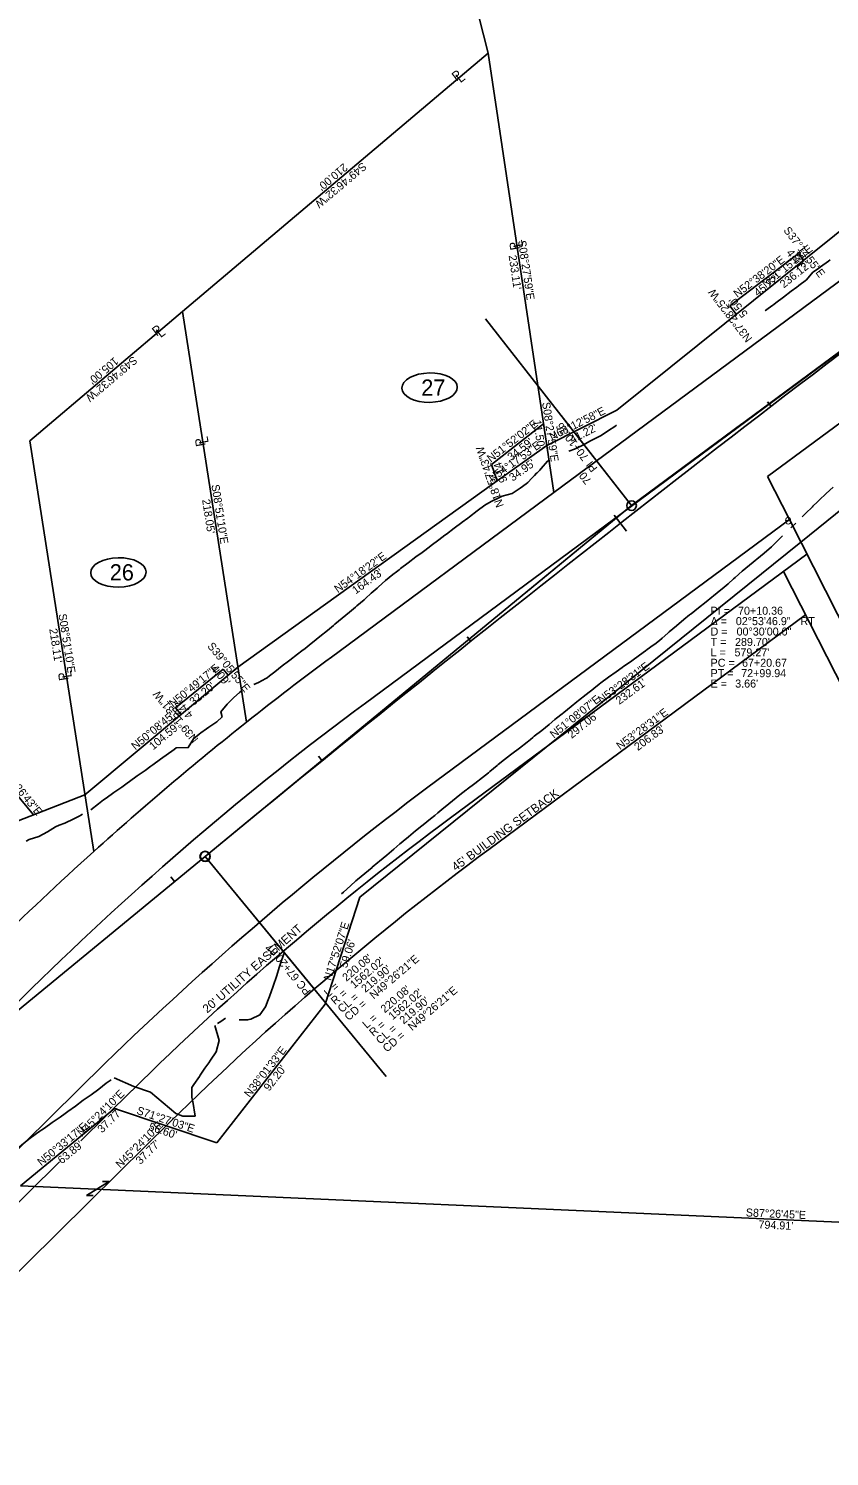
# Model space of a CAD drawing. Extents: x 1145508 to 2262867, y -3126236 to 2021677.
# Drawn here: x 1149547 to 1149967, y 2018793 to 2019543 of the extents above; entities that cross this region are included whole.
import ezdxf

# ---------------------------------------------------------------- set-up
doc = ezdxf.new("R2010")
doc.units = 0
for name, color, linetype in [('Default', 7, 'Continuous'), ('DSN_DRFT_Guideline-No-Plot', 7, 'Continuous'), ('DSN_RDWY_Alignment', 7, 'Continuous'), ('DSN_RDWY_Alignment Annotation', 7, 'Continuous'), ('DSN_RDWY_Const Limits', 7, 'Continuous'), ('DSN_ROW_Annotation', 7, 'Continuous'), ('DSN_ROW_Esmnt', 7, 'Continuous'), ('DSN_ROW_Line', 7, 'Continuous'), ('DSN_ROW_Line-Annotation', 7, 'Continuous'), ('DSN_ROW_Prop-Line', 7, 'Continuous'), ('DSN_ROW_Prop-Line-Annotation', 7, 'Continuous'), ('E_Const Align', 7, 'Continuous'), ('EX_QSECTION', 7, 'Continuous'), ('EX_ROW', 7, 'Continuous'), ('EX_ROW_ANNOT', 7, 'Continuous')]:
    doc.layers.add(name, color=color, linetype=linetype)

msp = doc.modelspace()

# ---------------------------------------------------------------- linework, layer by layer
at = {"layer": 'Default'}
for p, q in [((1150568.87, 2019814.51), (1149723.97, 2019188.76)), ((1149548.89, 2019038.9), (1148996.69, 2018494.41))]:
    msp.add_line(p, q, dxfattribs=at)
msp.add_arc((1150698.28, 2017873.24), 1637.02, 126.5246, 134.5973, dxfattribs=at)
at = {"layer": 'DSN_RDWY_Alignment'}
for p, q in [((1149863.59, 2019292.35), (1150096.32, 2019464.87)), ((1149639.88, 2019108.3), (1149863.59, 2019292.35))]:
    msp.add_line(p, q, dxfattribs=at)
for points in [[(1149863.59, 2019292.35), (1149787.06, 2019390.33)], [(1149639.88, 2019108.3), (1149734.93, 2018992.77)]]:
    msp.add_lwpolyline(points, dxfattribs=at)
for centre in [(1149863.59, 2019292.35), (1149639.88, 2019108.3)]:
    msp.add_circle(centre, 2.5, dxfattribs=at)
at = {"layer": 'DSN_RDWY_Alignment Annotation'}
for p, q in [((1149934.92, 2019346.79), (1149936.75, 2019344.41)), ((1149863.59, 2019292.35), (1149826.66, 2019339.64)), ((1149826.66, 2019339.64), (1149826.66, 2019339.64)), ((1149863.59, 2019292.35), (1149921.44, 2019335.23)), ((1149863.59, 2019292.35), (1149807.99, 2019246.61)), ((1149854.44, 2019287.33), (1149860.99, 2019278.96)), ((1149777.38, 2019223.49), (1149779.25, 2019221.15)), ((1149699.43, 2019160.82), (1149701.32, 2019158.49)), ((1149639.88, 2019108.3), (1149639.88, 2019108.3)), ((1149641.58, 2019106.23), (1149697.06, 2019038.8)), ((1149622.01, 2019097.48), (1149623.92, 2019095.17)), ((1149697.06, 2019038.8), (1149697.06, 2019038.8))]:
    msp.add_line(p, q, dxfattribs=at)
msp.add_circle((1149639.88, 2019108.3), 2.67, dxfattribs=at)
at = {"layer": 'DSN_RDWY_Const Limits'}
for p, q in [((1149933.84, 2019394.8), (1149933.59, 2019394.64)), ((1149813.81, 2019309.34), (1149814.09, 2019309.64))]:
    msp.add_line(p, q, dxfattribs=at)
for points in [[(1149933.84, 2019394.8), (1149935.26, 2019395.75), (1149937.66, 2019397.57), (1149938.2, 2019397.97), (1149939.26, 2019398.78), (1149943.26, 2019401.81), (1149947.27, 2019404.83), (1149950.2, 2019407.03), (1149951.08, 2019407.7), (1149951.28, 2019407.85), (1149955.3, 2019410.86), (1149958.61, 2019414.79), (1149961.58, 2019416.87), (1149962.72, 2019417.67), (1149966.81, 2019420.59), (1149967.8, 2019421.29)], [(1149830.76, 2019320.89), (1149833.71, 2019321.96), (1149838.33, 2019324.2), (1149841.65, 2019326.21), (1149842.71, 2019326.74), (1149847.29, 2019329.03), (1149848.2, 2019329.54), (1149851.54, 2019331.74), (1149854.76, 2019333.85), (1149855.74, 2019334.52)], [(1149814.09, 2019309.64), (1149815.41, 2019311.02), (1149816.15, 2019311.81), (1149819.55, 2019315.61), (1149820.38, 2019316.55)], [(1149665.48, 2019198.56), (1149667.97, 2019199.6), (1149671.79, 2019201.55), (1149672.44, 2019202.06), (1149673.62, 2019202.98), (1149676.4, 2019205.15), (1149680.38, 2019208.21), (1149683.7, 2019210.73), (1149684.38, 2019211.26), (1149688.34, 2019214.35), (1149690.67, 2019216.17), (1149692.33, 2019217.41), (1149695.57, 2019219.94), (1149696.27, 2019220.52), (1149700.15, 2019223.7), (1149704.03, 2019226.89), (1149707.18, 2019229.48), (1149707.44, 2019229.7), (1149707.91, 2019230.08), (1149711.81, 2019233.25), (1149715.66, 2019236.48), (1149718.75, 2019239.08), (1149719.51, 2019239.71), (1149723.32, 2019242.97), (1149723.96, 2019243.55), (1149727.05, 2019246.36), (1149730.07, 2019249.11), (1149730.77, 2019249.74), (1149734.5, 2019253.12), (1149738.41, 2019256.28), (1149740.26, 2019257.67), (1149741.63, 2019258.73), (1149742.41, 2019259.32), (1149746.39, 2019262.38), (1149750.41, 2019265.4), (1149753.67, 2019267.7), (1149754.5, 2019268.33), (1149757.51, 2019270.61), (1149758.5, 2019271.37), (1149762.51, 2019274.4), (1149765.66, 2019276.78), (1149766.52, 2019277.43), (1149770.53, 2019280.45), (1149774.53, 2019283.49), (1149774.7, 2019283.62), (1149777.66, 2019285.84), (1149778.54, 2019286.51), (1149782.55, 2019289.54), (1149786.56, 2019292.57), (1149789.97, 2019294.58), (1149790.98, 2019295.08), (1149792.53, 2019295.81), (1149795.64, 2019297.27), (1149800.92, 2019298.68), (1149804.16, 2019300.86), (1149805.08, 2019301.52), (1149808.34, 2019303.87), (1149809.11, 2019304.52), (1149811.32, 2019306.77), (1149812.66, 2019308.13), (1149813.81, 2019309.34)], [(1149952.99, 2019286.44), (1149954.84, 2019288.22), (1149958.43, 2019291.71), (1149958.71, 2019291.99), (1149961.06, 2019294.29), (1149962, 2019295.22), (1149965.59, 2019298.73), (1149969.32, 2019302.03)], [(1149947.13, 2019280.7), (1149947.67, 2019281.22), (1149949.7, 2019283.23)], [(1149711.4, 2019088.55), (1149712.47, 2019089.47), (1149716.12, 2019092.86), (1149718.98, 2019095.48), (1149719.83, 2019096.19), (1149723.66, 2019099.36), (1149727.49, 2019102.53), (1149727.52, 2019102.55), (1149730.5, 2019105.02), (1149731.33, 2019105.7), (1149735.14, 2019108.9), (1149738.93, 2019112.12), (1149742.11, 2019114.81), (1149742.73, 2019115.33), (1149743.86, 2019116.29), (1149746.53, 2019118.55), (1149750.32, 2019121.76), (1149753.56, 2019124.32), (1149754.22, 2019124.85), (1149758.13, 2019127.93), (1149760.39, 2019129.79), (1149761.97, 2019131.09), (1149765.11, 2019133.69), (1149765.8, 2019134.26), (1149769.65, 2019137.41), (1149773.51, 2019140.55), (1149776.67, 2019143.06), (1149776.94, 2019143.26), (1149777.42, 2019143.63), (1149781.4, 2019146.61), (1149785.38, 2019149.6), (1149788.46, 2019152.16), (1149789.21, 2019152.78), (1149793.04, 2019155.96), (1149793.69, 2019156.5), (1149796.9, 2019159.09), (1149800.12, 2019161.53), (1149800.87, 2019162.09), (1149804.82, 2019165.12), (1149808.77, 2019168.14), (1149810.51, 2019169.64), (1149811.81, 2019170.75), (1149812.55, 2019171.37), (1149816.48, 2019174.42), (1149820.37, 2019177.53), (1149823.37, 2019180.09), (1149824.17, 2019180.74), (1149827.11, 2019183.05), (1149828.08, 2019183.81), (1149831.96, 2019186.92), (1149834.94, 2019189.46), (1149835.78, 2019190.11), (1149839.71, 2019193.16), (1149843.61, 2019196.24), (1149843.78, 2019196.38), (1149846.6, 2019198.71), (1149847.49, 2019199.36), (1149851.53, 2019202.27), (1149855.57, 2019205.18), (1149858.73, 2019207.45), (1149859.61, 2019208.09), (1149860.96, 2019209.05), (1149863.66, 2019210.99), (1149867.7, 2019213.89), (1149870.84, 2019216.14), (1149871.75, 2019216.79), (1149874.99, 2019219.11), (1149875.8, 2019219.69), (1149878.25, 2019221.59), (1149879.63, 2019222.86), (1149882.53, 2019225.5), (1149883.35, 2019226.18), (1149887.17, 2019229.36), (1149891, 2019232.54), (1149894.03, 2019234.98), (1149894.55, 2019235.4), (1149894.88, 2019235.66), (1149898.75, 2019238.78), (1149902.64, 2019241.88), (1149905.62, 2019244.27), (1149906.52, 2019244.99), (1149910.4, 2019248.11), (1149911.18, 2019248.77), (1149914.18, 2019251.35), (1149917.03, 2019253.87), (1149917.92, 2019254.64), (1149921.67, 2019257.93), (1149925.46, 2019261.16), (1149927.37, 2019262.72), (1149928.39, 2019263.54), (1149929.32, 2019264.29), (1149933.13, 2019267.49), (1149936.92, 2019270.72), (1149939.65, 2019273.33), (1149940.53, 2019274.18), (1149942.81, 2019276.42)], [(1149580.04, 2019132.77), (1149584, 2019135.82), (1149586.69, 2019137.89), (1149587.98, 2019138.84), (1149592.06, 2019141.76), (1149596.14, 2019144.67), (1149599.07, 2019146.76), (1149600.22, 2019147.58), (1149604.29, 2019150.5), (1149604.84, 2019150.89), (1149608.39, 2019153.43), (1149611.46, 2019155.61), (1149612.49, 2019156.35), (1149616.57, 2019159.29), (1149620.66, 2019162.23), (1149622.4, 2019163.48), (1149623.7, 2019164.41), (1149624.75, 2019165.17), (1149631.05, 2019165.4), (1149633.73, 2019170.05), (1149636.84, 2019172.46), (1149637.72, 2019173.1), (1149640.62, 2019175.24), (1149641.77, 2019176.09), (1149645.99, 2019178.86), (1149648.9, 2019181.48), (1149648.22, 2019184.08), (1149651.43, 2019188.09), (1149655.03, 2019191.63), (1149655.05, 2019191.65), (1149657.89, 2019194.36), (1149658.73, 2019195.03), (1149659.41, 2019195.42)], [(1149546.1, 2019116.24), (1149547.6, 2019117.1), (1149552.67, 2019118.8), (1149557.21, 2019121.15), (1149559.98, 2019122.94), (1149561.47, 2019123.86), (1149563.43, 2019124.62), (1149566.37, 2019125.77), (1149571.04, 2019127.96), (1149574.11, 2019129.59), (1149574.64, 2019129.88), (1149575.54, 2019130.36)], [(1149657.78, 2019022.53), (1149662.22, 2019022.5), (1149662.89, 2019022.62), (1149663.92, 2019022.94), (1149668.66, 2019025.05), (1149671.64, 2019029.29), (1149672.95, 2019033.04), (1149673.6, 2019034.79), (1149675.6, 2019040.22), (1149677.52, 2019045.75), (1149678.77, 2019049.89), (1149679.27, 2019051.49), (1149681.16, 2019057.07), (1149681.42, 2019057.81)], [(1149592.17, 2018992.1), (1149602.46, 2018987.46), (1149611.33, 2018984.55), (1149624.54, 2018973.44), (1149628.15, 2018971.98), (1149634.62, 2018971.99), (1149633.55, 2018979.58), (1149633, 2018981.82), (1149632.91, 2018986.98), (1149633.96, 2018988.53), (1149636.9, 2018992.83), (1149637.28, 2018993.39), (1149639.83, 2018997.13), (1149641.77, 2018999.97), (1149642.77, 2019001.43), (1149645.7, 2019005.73), (1149647.32, 2019011.63), (1149645.05, 2019019.54)], [(1149646.41, 2019020.62), (1149648.1, 2019021.71), (1149650.56, 2019023.44)], [(1149528.11, 2018944.05), (1149530.65, 2018946.11), (1149531.99, 2018947.2), (1149535.86, 2018950.37), (1149539.74, 2018953.53), (1149542.23, 2018955.56), (1149543.61, 2018956.68), (1149547.49, 2018959.84), (1149551.48, 2018962.86), (1149553.13, 2018964), (1149554.34, 2018964.84), (1149555.6, 2018965.72), (1149559.72, 2018968.59), (1149563.81, 2018971.49), (1149566.45, 2018973.36), (1149567.89, 2018974.39), (1149571.98, 2018977.29), (1149575.92, 2018980.37), (1149578.55, 2018982.18), (1149580.12, 2018983.14), (1149584.19, 2018986.06), (1149588.03, 2018989.26), (1149590.65, 2018991.09)]]:
    msp.add_lwpolyline(points, dxfattribs=at)
at = {"layer": 'DSN_ROW_Esmnt'}
for p, q in [((1149915.19, 2019397.19), (1149951.12, 2019424.63)), ((1149951.12, 2019424.63), (1149953.79, 2019421.12)), ((1149918.53, 2019392.83), (1149915.19, 2019397.19)), ((1149790.16, 2019313.98), (1149817.37, 2019335.34)), ((1149817.37, 2019335.34), (1149819.06, 2019323.97)), ((1149793.13, 2019305.33), (1149790.16, 2019313.98)), ((1149624.45, 2019186.17), (1149649.41, 2019206.51)), ((1149649.41, 2019206.51), (1149651.99, 2019203.33)), ((1149627.28, 2019182.71), (1149624.45, 2019186.17)), ((1149533.36, 2019150.15), (1149549.85, 2019130.11))]:
    msp.add_line(p, q, dxfattribs=at)
at = {"layer": 'DSN_ROW_Line'}
for p, q in [((1149855.86, 2019342.54), (1150040.02, 2019490.31)), ((1149952.32, 2019273.26), (1150109.19, 2019399.67)), ((1149819.06, 2019323.97), (1149855.86, 2019342.54)), ((1149790.68, 2019303.57), (1149819.06, 2019323.97)), ((1149657.14, 2019207.63), (1149790.68, 2019303.57)), ((1149721.02, 2019086.86), (1149952.32, 2019273.26)), ((1149576.85, 2019140.61), (1149657.14, 2019207.63)), ((1149487.33, 2019105.8), (1149576.85, 2019140.61)), ((1149702.9, 2019030.65), (1149721.02, 2019086.86)), ((1149646.11, 2018958.02), (1149702.9, 2019030.65)), ((1149543.1, 2018935.44), (1149592.44, 2018976.03)), ((1149592.44, 2018976.03), (1149646.11, 2018958.02))]:
    msp.add_line(p, q, dxfattribs=at)
at = {"layer": 'DSN_ROW_Line-Annotation'}
for centre in [(1149757.65, 2019354.26), (1149594.42, 2019257.31)]:
    msp.add_ellipse(centre, major_axis=(14.54, 0.23), ratio=0.529773, dxfattribs=at)
at = {"layer": 'DSN_ROW_Prop-Line'}
for p, q in [((1149710.44, 2019832.55), (1149788.42, 2019529.81)), ((1149788.42, 2019529.81), (1149628.08, 2019394.19)), ((1149788.42, 2019529.81), (1149822.74, 2019299.24)), ((1149628.08, 2019394.19), (1149547.91, 2019326.39)), ((1149628.08, 2019394.19), (1149661.64, 2019178.75)), ((1149547.91, 2019326.39), (1149581.48, 2019110.87)), ((1149946.36, 2019285.02), (1150027.42, 2019125.25)), ((1149768.61, 2019128.48), (1149955.54, 2019266.93)), ((1149943.31, 2019257.87), (1150019.77, 2019107.18)), ((1149788.69, 2019111.93), (1149954.9, 2019235.03)), ((1149574.65, 2018958.97), (1149601.55, 2018985.49)), ((1149594.73, 2018942.42), (1149621.63, 2018968.94)), ((1149295.7, 2018683.91), (1149563.53, 2018948)), ((1149320.31, 2018671.82), (1149594.73, 2018942.42))]:
    msp.add_line(p, q, dxfattribs=at)
for centre in [(1150698.28, 2017873.24), (1150718.36, 2017856.69)]:
    msp.add_arc(centre, 1562.02, 126.5246, 134.5973, dxfattribs=at)
at = {"layer": 'DSN_ROW_Prop-Line-Annotation'}
for p, q in [((1149577.71, 2018930.36), (1149589.56, 2018937.74)), ((1149589.56, 2018937.74), (1149586.01, 2018937.74)), ((1149581.25, 2018930.36), (1149577.71, 2018930.36))]:
    msp.add_line(p, q, dxfattribs=at)
at = {"layer": 'E_Const Align'}
msp.add_line((1148677.53, 2018316.54), (1149639.88, 2019108.3), dxfattribs=at)
msp.add_arc((1156920.36, 2010259.18), 11459.16, 126.548983, 129.445337, dxfattribs=at)
msp.add_arc((1156920.36, 2010259.18), 11459.16, 126.548983, 129.445337, dxfattribs=at)
at = {"layer": 'EX_QSECTION'}
msp.add_line((1149543.1, 2018935.44), (1150337.23, 2018900.01), dxfattribs=at)
at = {"layer": 'EX_ROW'}
for p, q in [((1149822.74, 2019299.24), (1150218.47, 2019592.32)), ((1149934.89, 2019307.63), (1150095.5, 2019426.58)), ((1149946.36, 2019285.02), (1149934.89, 2019307.63)), ((1149706.12, 2019212.86), (1149822.74, 2019299.24)), ((1149756.71, 2019144.56), (1149946.36, 2019285.02)), ((1149952.32, 2019273.26), (1149946.36, 2019285.02)), ((1149523.2, 2018936.33), (1149587.51, 2018999.73))]:
    msp.add_line(p, q, dxfattribs=at)
for centre, radius, start, end in [((1150698.28, 2017873.24), 1667.02, 126.5246, 128.45139), ((1150698.28, 2017873.24), 1667.02, 128.45139, 132.0621), ((1150799.18, 2017755.35), 1736.85, 126.88494, 134.23696), ((1150698.28, 2017873.24), 1667.02, 132.0621, 134.5973)]:
    msp.add_arc(centre, radius, start, end, dxfattribs=at)

# ---------------------------------------------------------------- texts
at = {"layer": 'DSN_DRFT_Guideline-No-Plot'}
for rotation, p in [(352.30493, (1149951.08, 2019424.59)), (262.99544, (1149953.75, 2019421.16)), (82.41743, (1149915.23, 2019397.15)), (354.13868, (1149649.37, 2019206.46)), (84.21868, (1149624.5, 2019186.13))]:
    msp.add_text('+', height=0.1, rotation=rotation, dxfattribs=at).set_placement(p)
for p in [(1149952.79, 2019420.12), (1149917.53, 2019391.83)]:
    msp.add_text('b', height=2, dxfattribs=at).set_placement(p)
at = {"layer": 'DSN_RDWY_Alignment Annotation'}
for s, rotation, p in [('70+10.36', 127.99716, (1149841.38, 2019317.86)), ('PI ', 127.99716, (1149845.95, 2019312.02)), ('70', 128.04868, (1149842.85, 2019305.54)), ('67+20.67', 129.44534, (1149689.63, 2019045)), ('PC', 129.44534, (1149695.67, 2019037.65))]:
    msp.add_text(s, height=4.2, rotation=rotation, dxfattribs=at).set_placement(p)
for s, p in [('PI = ', (1149905.04, 2019235.1)), ('70+10.36', (1149919.44, 2019235.1)), ('Δ = ', (1149905.04, 2019229.64)), ('D = ', (1149905.04, 2019224.18)), ('02°53\'46.9"', (1149918.27, 2019229.64)), ('00°30\'00.0"', (1149918.68, 2019224.18)), (' RT', (1149950.63, 2019229.64)), ('T = ', (1149905.04, 2019218.72)), ("289.70'", (1149917.85, 2019218.72)), ('L = ', (1149905.04, 2019213.26)), ("579.27'", (1149917.57, 2019213.26)), ('PC = ', (1149905.04, 2019207.8)), ('PT = ', (1149905.04, 2019202.34)), ('72+99.94', (1149921.09, 2019202.34)), ('67+20.67', (1149921.54, 2019207.8)), ('E = ', (1149905.04, 2019196.88)), ("3.66'", (1149917.96, 2019196.88))]:
    msp.add_text(s, height=4.2, dxfattribs=at).set_placement(p)
at = {"layer": 'DSN_ROW_Annotation'}
for s, rotation, p in [('S49°46\'32"W', 220.22439, (1149722.4, 2019472.79)), ("210.00'", 220.22439, (1149712.48, 2019472.26)), ('S37°14\'55"E', 307.24868, (1149943.03, 2019436.76)), ('S08°27\'59"E', 278.46629, (1149804, 2019431.23)), ("233.11'", 278.46629, (1149799.08, 2019423.52)), ('N52°38\'20"E', 37.36118, (1149919.05, 2019401.28)), ('N51°15\'28"E', 38.7422, (1149934.07, 2019406.45)), ("4.41'", 307.24868, (1149944.5, 2019424.92)), ("236.12'", 38.7422, (1149943.44, 2019406.28)), ("45.22'", 37.36118, (1149929.77, 2019401.91)), ('N37°28\'25"W', 127.47368, (1149927.13, 2019380.13)), ("5.50'", 127.47368, (1149924.83, 2019393)), ('S49°46\'32"W', 220.22439, (1149602.14, 2019371.08)), ("105.00'", 220.22439, (1149592.23, 2019370.55)), ('S08°27\'59"E', 278.46629, (1149816.64, 2019346.36)), ('N63°12\'58"E', 26.78377, (1149821.83, 2019326.37)), ('N51°52\'02"E', 38.13269, (1149789.79, 2019314.84)), ("11.50'", 278.46629, (1149811.97, 2019336.97)), ("41.22'", 26.78377, (1149832.48, 2019325.03)), ('N54°17\'53"E', 35.70194, (1149790.49, 2019304.54)), ("34.59'", 38.13269, (1149800.5, 2019315.61)), ('N18°57\'43"W', 108.9619, (1149796.66, 2019292.28)), ("9.14'", 108.9619, (1149798.56, 2019305.22)), ("34.95'", 35.70194, (1149801.23, 2019304.87)), ('S08°51\'10"E', 278.85286, (1149643.17, 2019303.17)), ("218.05'", 278.85286, (1149638.3, 2019295.43)), ('N54°18\'22"E', 35.69392, (1149709.53, 2019246.38)), ("164.43'", 35.69392, (1149718.88, 2019245.71)), ('S08°51\'10"E', 278.85286, (1149563, 2019235.33)), ("218.11'", 278.85286, (1149558.14, 2019227.59)), ('S39°05\'55"E', 309.09868, (1149640.83, 2019218.5)), ('N50°49\'17"E', 39.17868, (1149623.14, 2019186.26)), ("4.09'", 309.09868, (1149642.67, 2019206.71)), ('N53°28\'31"E', 36.5246, (1149847.83, 2019188.28)), ("32.20'", 39.17868, (1149633.83, 2019187.24)), ("232.61'", 36.5246, (1149857.19, 2019187.74)), ('N39°15\'31"W', 129.25868, (1149636.6, 2019169.88)), ('N51°08\'07"E', 38.8647, (1149822.83, 2019170.06)), ('N50°08\'45"E', 39.85429, (1149603.32, 2019163.88)), ("4.47'", 129.25868, (1149633.89, 2019182.67)), ("297.06'", 38.8647, (1149832.2, 2019169.91)), ('N53°28\'31"E', 36.5246, (1149857.55, 2019164.05)), ("104.59'", 39.85429, (1149612.69, 2019163.89)), ("206.83'", 36.5246, (1149866.91, 2019163.52)), ('S39°26\'43"E', 309.44534, (1149531.65, 2019153.65)), ('N17°52\'07"E', 72.1315, (1149705.87, 2019042.8)), ("59.06'", 72.1315, (1149714.31, 2019049.43)), ("220.08'", 40.56095, (1149714.05, 2019042.41)), ("1562.02'", 40.56095, (1149718.17, 2019038.75)), ('N49°26\'21"E', 40.56095, (1149728.38, 2019033.12)), ("219.90'", 40.56095, (1149723.99, 2019036.55)), ('L = ', 40.56095, (1149704.53, 2019034.27)), ("220.08'", 40.56095, (1149734.13, 2019025.86)), ('R = ', 40.56095, (1149708.08, 2019030.12)), ('CL = ', 40.56095, (1149711.63, 2019025.97)), ("1562.02'", 40.56095, (1149738.25, 2019022.2)), ("219.90'", 40.56095, (1149744.07, 2019019.99)), ('N49°26\'21"E', 40.56095, (1149748.46, 2019016.57)), ('CD = ', 40.56095, (1149715.18, 2019021.82)), ('L = ', 40.56095, (1149724.61, 2019017.71)), ('R = ', 40.56095, (1149728.16, 2019013.56)), ('CL = ', 40.56095, (1149731.71, 2019009.42)), ('CD = ', 40.56095, (1149735.26, 2019005.27)), ('N38°01\'33"E', 51.97414, (1149663.29, 2018981.45)), ("92.20'", 51.97414, (1149673.5, 2018984.77)), ('N45°24\'10"E', 44.5973, (1149575.32, 2018960.9)), ("37.77'", 44.5973, (1149585.88, 2018962.88)), ('S71°27\'03"E', 341.45072, (1149603.67, 2018973.21)), ('N50°33\'17"E', 39.44534, (1149554.03, 2018945.59)), ('N45°24\'10"E', 44.5973, (1149595.4, 2018944.34)), ("56.60'", 341.45072, (1149609.92, 2018964.79)), ("63.89'", 39.44534, (1149564.72, 2018946.62)), ("37.77'", 44.5973, (1149605.96, 2018946.32))]:
    msp.add_text(s, height=4.2, rotation=rotation, dxfattribs=at).set_placement(p)
at = {"layer": 'DSN_ROW_Esmnt'}
for p in [(1149950.12, 2019423.63), (1149914.19, 2019396.19), (1149789.16, 2019312.98)]:
    msp.add_text('b', height=2, dxfattribs=at).set_placement(p)
at = {"layer": 'DSN_ROW_Line-Annotation'}
for s, p in [('27', (1149753.27, 2019350.05)), ('26', (1149589.9, 2019253.1))]:
    msp.add_text(s, height=8.5, dxfattribs=at).set_placement(p)
at = {"layer": 'DSN_ROW_Prop-Line'}
for s, rotation, p in [("45' BUILDING SETBACK", 36.28304, (1149771.35, 2019100.32)), ("20' UTILITY EASEMENT", 41.12494, (1149641, 2019025.77))]:
    msp.add_text(s, height=4.5, rotation=rotation, dxfattribs=at).set_placement(p)
at = {"layer": 'DSN_ROW_Prop-Line-Annotation'}
for s, rotation, p in [('P', 37.94139, (1149771.71, 2019514.77)), ('L', 37.94139, (1149773.81, 2019513.97)), ('P', 100.49967, (1149805.05, 2019426.93)), ('L', 100.49967, (1149806.72, 2019428.43)), ('P', 37.94139, (1149614.51, 2019381.01)), ('L', 37.94139, (1149616.61, 2019380.22)), ('P', 100.49967, (1149640.15, 2019323.88)), ('L', 100.49967, (1149641.82, 2019325.37)), ('L', 98.42002, (1149570.04, 2019202.32)), ('P', 98.42002, (1149568.31, 2019200.88))]:
    msp.add_text(s, height=5, rotation=rotation, dxfattribs=at).set_placement(p)
at = {"layer": 'EX_ROW'}
msp.add_text('e', height=5, dxfattribs=at).set_placement((1149943.86, 2019282.52))
at = {"layer": 'EX_ROW_ANNOT'}
for s, p in [('S87°26\'45"E', (1149923.46, 2018919.37)), ('S87°26\'45"E', (1149923.46, 2018919.37)), ("794.91'", (1149930.09, 2018913.07)), ("794.91'", (1149930.09, 2018913.07))]:
    msp.add_text(s, height=4.2, rotation=357.44576, dxfattribs=at).set_placement(p)

doc.saveas('drawing.dxf')
